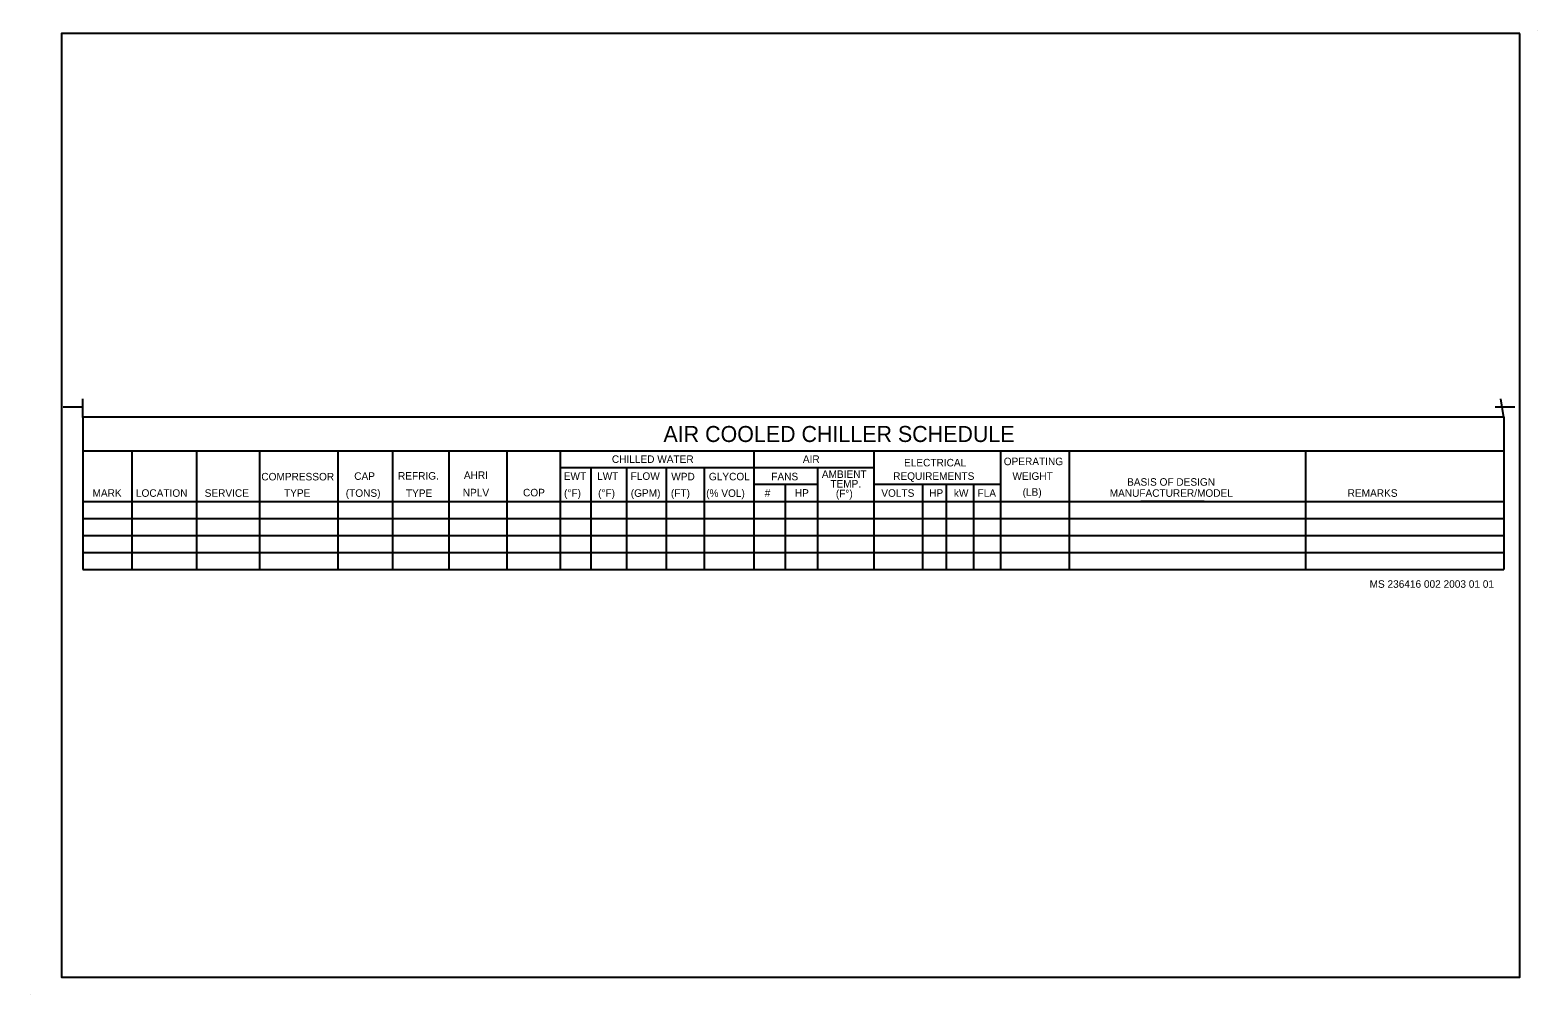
# Model space of a CAD drawing. Extents: x 10179 to 10312, y 10254 to 10340.
import ezdxf

# ---------------------------------------------------------------- set-up
doc = ezdxf.new("R2010")
doc.units = 0
for name, color, linetype in [('G-ANNO-PD', 7, 'Continuous'), ('G-ANNO-TEXT', 7, 'Continuous'), ('G-DETL-GRID', 7, 'Continuous'), ('G-DETL-LINE', 7, 'Continuous'), ('G-SCHD-LINE', 7, 'Continuous'), ('G-SCHD-TTXT', 7, 'Continuous')]:
    doc.layers.add(name, color=color, linetype=linetype)

msp = doc.modelspace()

# ---------------------------------------------------------------- linework, layer by layer
at = {"layer": 'G-ANNO-PD'}
for p, q in [((10312.05, 10339.59), (10312.05, 10339.59)), ((10178.69, 10254.23), (10178.69, 10254.23))]:
    msp.add_line(p, q, dxfattribs=at)
at = {"layer": 'G-DETL-GRID'}
msp.add_lwpolyline([(10310.45, 10339.29), (10181.47, 10339.29), (10181.47, 10255.81), (10310.45, 10255.81)], close=True, dxfattribs=at)
at = {"layer": 'G-DETL-LINE'}
for p, q in [((10183.35, 10306.22), (10181.62, 10306.22)), ((10183.35, 10305.31), (10183.35, 10306.97)), ((10310.02, 10306.22), (10308.27, 10306.22)), ((10309.04, 10305.31), (10308.77, 10306.97))]:
    msp.add_line(p, q, dxfattribs=at)
at = {"layer": 'G-SCHD-LINE'}
for p, q in [((10183.35, 10305.38), (10309.04, 10305.38)), ((10183.35, 10305.38), (10183.35, 10291.88)), ((10309.04, 10305.38), (10309.04, 10291.88)), ((10183.35, 10302.38), (10309.04, 10302.38)), ((10187.68, 10302.38), (10187.68, 10297.88)), ((10193.41, 10302.38), (10193.41, 10297.88)), ((10198.97, 10302.38), (10198.97, 10297.88)), ((10205.9, 10302.38), (10205.9, 10297.88)), ((10210.73, 10302.38), (10210.73, 10291.88)), ((10215.73, 10302.38), (10215.73, 10291.88)), ((10220.85, 10302.38), (10220.85, 10291.88)), ((10225.56, 10302.38), (10225.56, 10297.88)), ((10242.71, 10302.38), (10242.71, 10297.88)), ((10253.31, 10302.38), (10253.31, 10297.88)), ((10253.33, 10302.38), (10253.33, 10297.88)), ((10253.33, 10302.38), (10253.33, 10297.88)), ((10264.51, 10302.38), (10264.51, 10291.88)), ((10270.61, 10302.38), (10270.61, 10291.88)), ((10291.5, 10302.38), (10291.5, 10291.88)), ((10225.56, 10300.88), (10229.89, 10300.88)), ((10228.29, 10300.88), (10228.29, 10291.88)), ((10229.89, 10300.88), (10234.23, 10300.88)), ((10231.44, 10300.88), (10231.44, 10291.88)), ((10234.23, 10300.88), (10238.56, 10300.88)), ((10234.95, 10300.88), (10234.95, 10291.88)), ((10238.3, 10300.88), (10238.3, 10291.88)), ((10238.56, 10300.88), (10242.71, 10300.88)), ((10242.71, 10300.88), (10253.33, 10300.88)), ((10248.34, 10300.88), (10248.34, 10291.88)), ((10248.34, 10299.38), (10242.71, 10299.38)), ((10245.48, 10299.38), (10245.48, 10291.88)), ((10257.62, 10299.38), (10253.33, 10299.38)), ((10257.62, 10299.38), (10257.62, 10297.88)), ((10259.73, 10299.38), (10257.62, 10299.38)), ((10259.73, 10299.38), (10259.73, 10297.88)), ((10264.43, 10299.38), (10259.73, 10299.38)), ((10262.12, 10299.38), (10262.12, 10291.88)), ((10183.35, 10297.88), (10187.68, 10297.88)), ((10187.68, 10297.88), (10187.68, 10291.88)), ((10187.68, 10297.88), (10276.84, 10297.88)), ((10193.41, 10297.88), (10193.41, 10291.88)), ((10198.97, 10297.88), (10198.97, 10291.88)), ((10205.9, 10297.88), (10205.9, 10291.88)), ((10225.56, 10297.88), (10225.56, 10291.88)), ((10242.71, 10297.88), (10242.71, 10291.88)), ((10253.31, 10297.88), (10253.31, 10291.88)), ((10253.33, 10297.88), (10253.33, 10291.88)), ((10253.33, 10297.88), (10253.33, 10291.88)), ((10257.62, 10297.88), (10257.62, 10291.88)), ((10259.73, 10297.88), (10259.73, 10291.88)), ((10272.03, 10297.88), (10309.04, 10297.88)), ((10276.95, 10297.88), (10276.95, 10297.88)), ((10282.53, 10297.88), (10276.95, 10297.88)), ((10276.95, 10297.88), (10282.53, 10297.88)), ((10183.35, 10296.38), (10309.04, 10296.38)), ((10183.35, 10294.88), (10309.04, 10294.88)), ((10183.35, 10293.38), (10309.04, 10293.38)), ((10183.35, 10291.88), (10309.04, 10291.88))]:
    msp.add_line(p, q, dxfattribs=at)

# ---------------------------------------------------------------- texts
at = {"layer": 'G-ANNO-TEXT'}
for s, height, p in [('CHILLED WATER', 0.6667, (10230.15, 10301.3)), ('AIR', 0.667, (10247.04, 10301.3)), ('ELECTRICAL', 0.667, (10255.99, 10300.99)), ('OPERATING', 0.667, (10264.81, 10301.1)), ('COMPRESSOR', 0.667, (10199.14, 10299.75)), ('CAP', 0.667, (10207.36, 10299.8)), ('REFRIG.', 0.667, (10211.23, 10299.82)), ('AHRI', 0.667, (10217.06, 10299.88)), ('EWT', 0.667, (10225.89, 10299.8)), ('LWT', 0.667, (10228.84, 10299.8)), ('FLOW', 0.667, (10231.81, 10299.8)), ('WPD', 0.667, (10235.4, 10299.76)), ('GLYCOL', 0.667, (10238.73, 10299.76)), ('FANS', 0.667, (10244.25, 10299.76)), ('AMBIENT', 0.667, (10248.72, 10299.97)), ('TEMP.', 0.667, (10249.47, 10299.12)), ('REQUIREMENTS', 0.6667, (10255.03, 10299.8)), ('WEIGHT', 0.667, (10265.58, 10299.8)), ('BASIS OF DESIGN', 0.6667, (10275.72, 10299.28)), ('MARK', 0.667, (10184.21, 10298.3)), ('LOCATION', 0.667, (10188.05, 10298.3)), ('SERVICE', 0.667, (10194.13, 10298.3)), ('TYPE', 0.667, (10201.15, 10298.3)), ('(TONS)', 0.667, (10206.61, 10298.3)), ('TYPE', 0.667, (10211.93, 10298.29)), ('NPLV', 0.667, (10216.96, 10298.34)), ('COP', 0.667, (10222.29, 10298.34)), ('(°F)', 0.667, (10225.92, 10298.3)), ('(°F)', 0.667, (10228.93, 10298.3)), ('(GPM)', 0.667, (10231.82, 10298.3)), ('(FT)', 0.667, (10235.37, 10298.3)), ('(% VOL)', 0.667, (10238.49, 10298.29)), ('#', 0.667, (10243.67, 10298.31)), ('HP', 0.667, (10246.33, 10298.31)), ('(F°)', 0.667, (10249.96, 10298.26)), ('VOLTS', 0.667, (10253.98, 10298.3)), ('HP', 0.667, (10258.21, 10298.3)), ('kW', 0.667, (10260.4, 10298.3)), ('FLA', 0.667, (10262.49, 10298.3)), ('(LB)', 0.667, (10266.48, 10298.39)), ('MANUFACTURER/MODEL', 0.6667, (10274.18, 10298.3)), ('REMARKS', 0.667, (10295.23, 10298.3)), ('MS 236416 002 2003 01 01', 0.6667, (10297.17, 10290.25))]:
    msp.add_text(s, height=height, dxfattribs=at).set_placement(p)
at = {"layer": 'G-SCHD-TTXT'}
msp.add_text('AIR COOLED CHILLER SCHEDULE', height=1.4167, dxfattribs=at).set_placement((10234.71, 10303.15))

doc.saveas('drawing.dxf')
